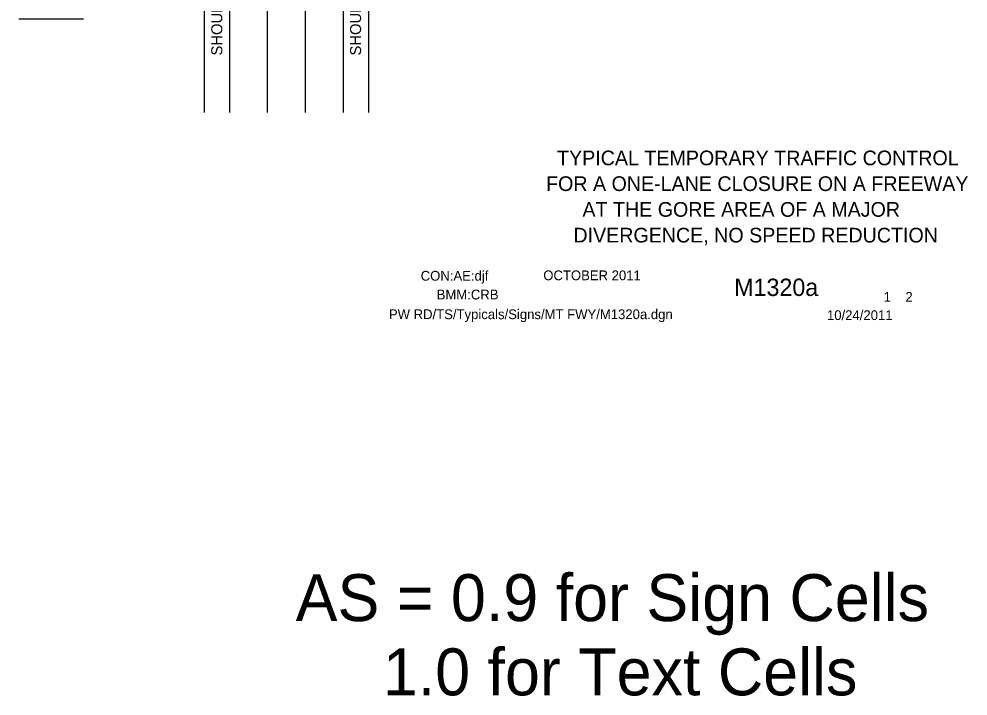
# Model space of a CAD drawing. Extents: x 16728 to 18475, y 6981 to 8243.
# Drawn here: x 16836 to 17437, y 6981 to 7410 of the extents above; entities that cross this region are included whole.
import ezdxf

# ---------------------------------------------------------------- set-up
doc = ezdxf.new("R2010")
doc.units = 0
for name, color, linetype in [('ALI_LEGAL_EX', 7, 'Continuous'), ('BORDER', 7, 'Continuous'), ('BORDER_SIGNAL_WO', 7, 'Continuous'), ('PAVT_EDGE_EX', 7, 'Continuous'), ('TRAFFIC_SIGNS_PR', 7, 'Continuous'), ('TYPICAL_TEXT_DIMEN_PR', 7, 'Continuous')]:
    doc.layers.add(name, color=color, linetype=linetype)

msp = doc.modelspace()

# ---------------------------------------------------------------- linework, layer by layer
at = {"layer": 'ALI_LEGAL_EX'}
for p, q in [((16993.65, 7350.77), (16993.65, 7723.56)), ((17017.65, 7350.77), (17017.65, 7723.56))]:
    msp.add_line(p, q, dxfattribs=at)
at = {"layer": 'PAVT_EDGE_EX'}
for p, q in [((16953.65, 7723.56), (16953.65, 7350.77)), ((16969.65, 7723.56), (16969.65, 7350.77)), ((17041.65, 7723.56), (17041.65, 7350.77)), ((17057.65, 7723.56), (17057.65, 7350.77))]:
    msp.add_line(p, q, dxfattribs=at)
at = {"layer": 'TRAFFIC_SIGNS_PR'}
msp.add_line((16836.34, 7410.02), (16877.29, 7410.02), dxfattribs=at)

# ---------------------------------------------------------------- texts
at = {"layer": 'BORDER'}
for s, p in [('TYPICAL TEMPORARY TRAFFIC CONTROL', (17177.02, 7317.4)), ('FOR A ONE-LANE CLOSURE ON A FREEWAY', (17170.07, 7301.1)), ('AT THE GORE AREA OF A MAJOR ', (17193.1, 7284.8)), ('DIVERGENCE, NO SPEED REDUCTION', (17187.38, 7268.5))]:
    msp.add_text(s, height=9.3, dxfattribs=at).set_placement(p)
at = {"layer": 'BORDER_SIGNAL_WO'}
for s, height, p in [('CON:AE:djf  ', 6.2, (17090.69, 7244.31)), ('    OCTOBER 2011    ', 6.2, (17159.08, 7244.59)), ('    M1320a   ', 11, (17272.86, 7234.63)), ('BMM:CRB   ', 6.2, (17100.81, 7232.42)), (' 1    2 ', 6.2, (17381.45, 7230.95)), ('PW RD/TS/Typicals/Signs/MT FWY/M1320a.dgn      ', 6.2, (17070.55, 7219.96)), ('10/24/2011    ', 6.2, (17347.93, 7219.38)), ('AS = 0.9 for Sign Cells', 29.7271, (17011.5, 7028.75)), ('     1.0 for Text Cells', 29.7271, (17011.5, 6981.75))]:
    msp.add_text(s, height=height, dxfattribs=at).set_placement(p)
at = {"layer": 'TYPICAL_TEXT_DIMEN_PR'}
for p in [(16965.09, 7386.89), (17052.95, 7386.89)]:
    msp.add_text('SHOULDER', height=7, rotation=90, dxfattribs=at).set_placement(p)

doc.saveas('drawing.dxf')
